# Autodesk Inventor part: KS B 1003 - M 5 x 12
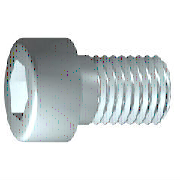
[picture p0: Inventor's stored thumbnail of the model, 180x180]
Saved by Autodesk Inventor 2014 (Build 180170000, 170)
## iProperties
Created: 2009-02
Part Number: KS B 1003 - M 5 x 12
Material: 강, 연강
Description: 6각머리 태핑 나사
Document SubType Name: Modeling
Standard: KS B 1003
Designer: KYOUNG IL JANG
Standards Organization: KS
Language: ko-KR
Size Designation: M 5 x 12
Categories: <MemberInstance><Categories><Category DisplayName="조임쇠" InternalName="e4da775c-781d-43d5-af7c-5136215cf5a6" Mnemonic="FSTN"><Category DisplayName="볼트" InternalN
Density: 7.86 g/cm^3
Appearance: 강철
Mass: 3.72825 g
Surface Area: 4.62573 cm^2
Volume: 0.474332 cm^3
IsCustomPart: 0
Author: KYOUNG IL JANG
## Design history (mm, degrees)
sketch "스케치1"
  geometry: L1 (-1.167, 0)-(12, 0); L2 (12, 0)-(12, 2.5); L3 (12, 2.5)-(2, 2.5); L4 (2, 2.5)-(1.509, 2.5); L5 (1.509, 2.5)-(0, 2.5); L6 (0, 2.5)-(0, 4.25); L7 (0, 4.25)-(-5, 4.25); L8 (-5, 4.25)-(-5, 2.309); L9 (-5, 2.309)-(-2.5, 2.309); L10 (-2.5, 2.309)-(-1.167, 0); L11 (-8.4, 0)-(15.4, 0) reference; L12 (0, -0.85)-(0, 5.1) reference; L13 (2, 2.5)-(0, 2.5)
  constraints: 22 end point, 6 parallel, 2 collinear, 2 perpendicular, 1 horizontal, 1 point on line
  dimensions: "d1" = 10 distance from line of L3.end L2 (= GEL); "d2" = 0.49086 distance of L4.end L3.end (computed from GAL); "d3" = 5 distance between parallel lines of L8 L6 (= KOH); "d4" = 2.5 distance of L8.end L9.end (= INTI); "d5" = 60 deg angle of L10 L1; "d6" = 5 diameter of L3 L1 (= GD); "d7" = 5 diameter of L5 L1 (= BDM); "d8" = 4.6188 diameter of L9 L1 (= 1.1547 x SW); "d9" = 8.5 diameter of L7 L1 (= KOD); "d26" = 12 distance between parallel lines of L12 L2 (= NLG)
revolve "본체" sketch "스케치1" stored, may be unused: angle "d10" = 90 deg
sketch "스케치2"
  geometry: L1 (0, -5.95)-(0, 5.95) reference; L2 (-5.95, 0)-(5.95, 0) reference; L3 (2.309, 0)-(1.155, -2); L4 (1.155, -2)-(-1.155, -2); L5 (-1.155, -2)-(-2.309, 0); L6 (-2.309, 0)-(-1.155, 2); L7 (-1.155, 2)-(1.155, 2); L8 (1.155, 2)-(2.309, 0); 2 further points
  constraints: 12 end point, 1 coincident, 1 horizontal alignment, 1 point on line, 12 other
extrude "슬롯" join sketch "스케치2" stored distance "d11" = 10; taper "d12" = 0 deg
workplane "Work Plane1"
fillet "Fillet2" dims "d30" = 0.1 (= R)
body "Solid1"
fillet "모깎기1" dims "d17" = 0.5 (= RR)
feature "스레드" dims "d13" = 10 (= GEL), "d14" = 0
chamfer "모따기1" distance "d15" = 0.49076 (= -0.5 x SPD + 0.5 x GD); stored, may be unused: second distance "d16" = 0.49076 (= GUL), angle "d27" = 45 deg
other parameters: "GD" = 5 (= NND) [user parameter; used in 2 equation terms], "NLG" = 12 [user parameter; used in 1 equation term], "GEL" = 10 [user parameter; used in 2 equation terms], "KOD" = 8.5 [user parameter; used in 1 equation term], "KOH" = 5 [user parameter; used in 1 equation term], "INTI" = 2.5 [user parameter; used in 1 equation term], "GAL" = 0.49076 (= 0.61345 x PTC) [user parameter; used in 1 equation term], "GUL" = 0.49076 (= 0.61345 x PTC) [user parameter; used in 1 equation term], "BDM" = 5 (= NND) [user parameter; used in 1 equation term], "SW" = 4 [user parameter; used in 2 equation terms], "RR" = 0.5 [user parameter; used in 1 equation term], "SPD" = 4.01848 (= NND - 1.2269 x PTC) [user parameter; used in 1 equation term], "d19" = 0, "d28" = 0, "d29" = 0, "R" = 0.1 [user parameter; used in 1 equation term], "PHH" = 0.2 [user parameter], "GD1" = 4.01848 (= THREADDIA - 1.2269 x PTC) [user parameter], "THREADDIA" = 5 [user parameter; used in 1 equation term], "FAWI" = 45 deg [user parameter], "TPU" = 12.5 (computed from PTC) [user parameter], "PTC" = 0.8 [user parameter; used in 5 equation terms], "NND" = 5 [user parameter; used in 3 equation terms], "TOA" = 30 deg [user parameter], "E0" = 4.62 (= 1.155 x SW) [user parameter]
